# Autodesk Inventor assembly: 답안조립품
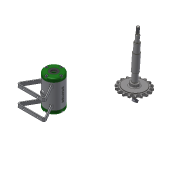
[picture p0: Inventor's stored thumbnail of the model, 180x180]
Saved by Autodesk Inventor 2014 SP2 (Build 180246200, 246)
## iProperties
Created: 2016-03
Part Number: 답안조립품
Document SubType Name: Assembly
Designer: 손기택
Author: 손기택
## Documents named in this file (12)
- C:\Users\201-15\Desktop\460307V1018\답안조립품.iam
- C:\Users\201-15\Desktop\460307V1018\본체.ipt
- C:\Users\201-15\Desktop\460307V1018\커버.ipt
- C:\Users\201-15\Desktop\460307V1018\오일 실 15 25 7.ipt
- C:\Users\201-15\Desktop\460307V1018\베어링 15 x 32 x 9.ipt
- C:\Users\201-15\Desktop\460307V1018\볼트 M4 x 12.ipt
- C:\Users\201-15\Desktop\460307V1018\축.ipt
- C:\Users\201-15\Desktop\460307V1018\키 3 x 3 x 12.ipt
- C:\Users\201-15\Desktop\460307V1018\스프로킷.ipt
- C:\Users\201-15\Desktop\460307V1018\스프링와셔 8.ipt
- C:\Users\201-15\Desktop\460307V1018\와셔 8x17.ipt
- C:\Users\201-15\Desktop\460307V1018\너트 M 8.ipt
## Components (10 placed, 2 different names)
1. KS B 2023 6002 - 15 x 32 x 9:1
2. KS B 2023 6002 - 15 x 32 x 9:2
3. ISO 4762 M4 x 12:1
4. ISO 4762 M4 x 12:2
5. ISO 4762 M4 x 12:3
6. ISO 4762 M4 x 12:4
7. ISO 4762 M4 x 12:5
8. ISO 4762 M4 x 12:6
9. ISO 4762 M4 x 12:7
10. ISO 4762 M4 x 12:8
